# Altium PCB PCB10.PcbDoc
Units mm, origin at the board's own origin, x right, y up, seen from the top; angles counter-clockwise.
Board outline 101.6 x 53.34 mm, 4 copper layers (TOP, GND, SIG, BOTTOM), stack 1.586 mm thick; 82 components, 223 nets, 746 pads, 0 vias.
Unrouted connection lines stored in the file: 269.
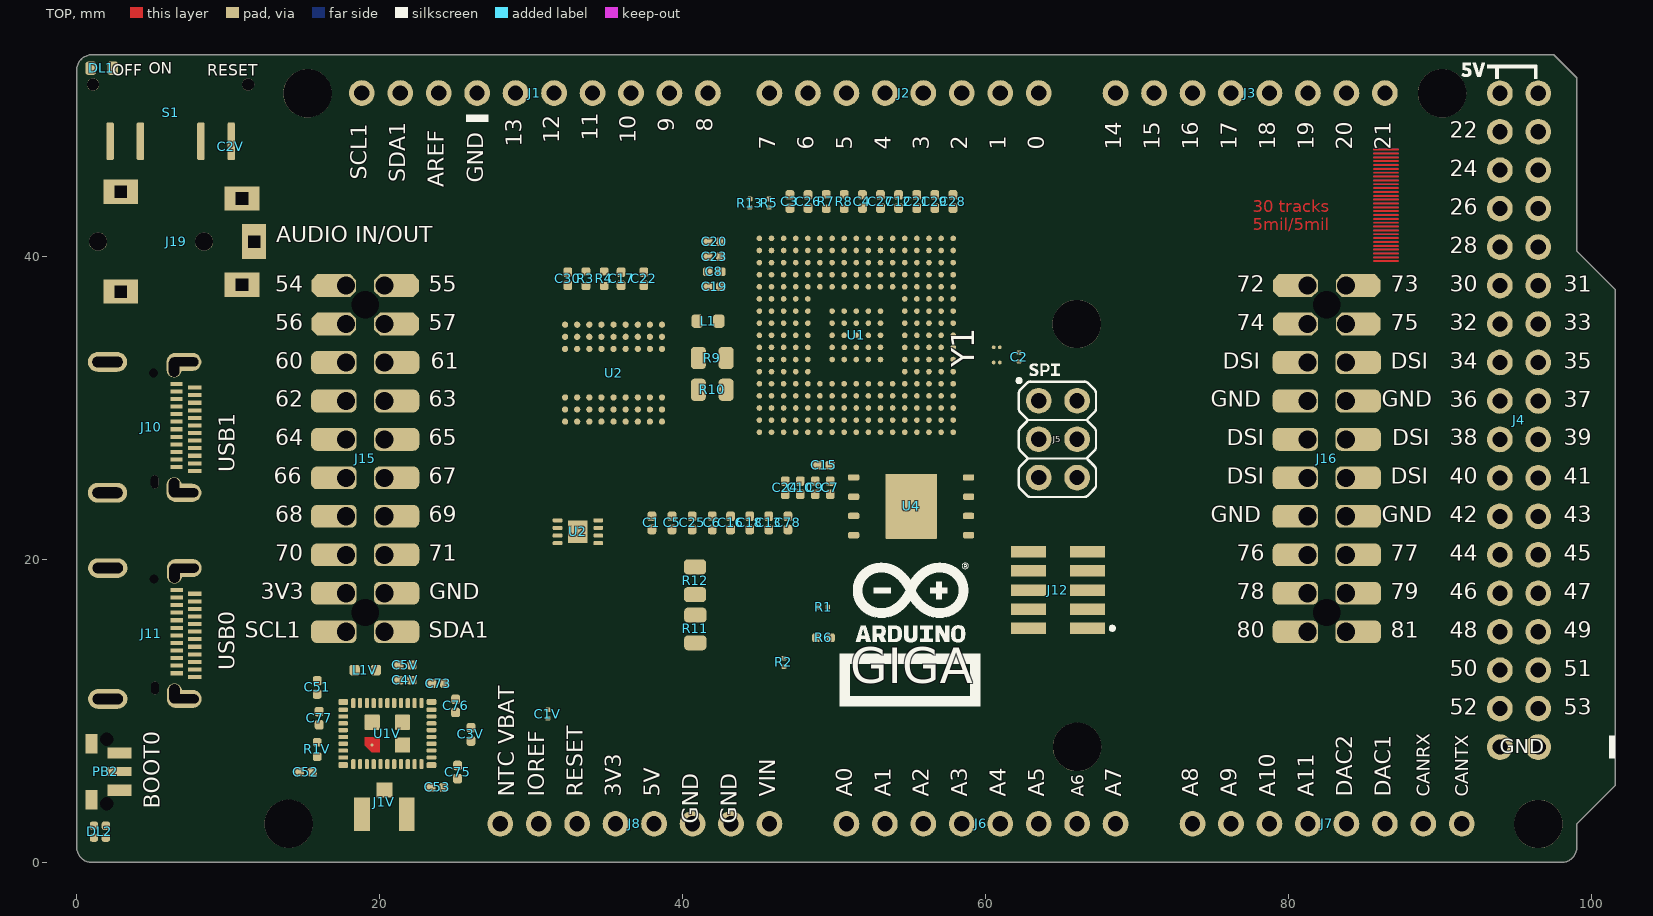
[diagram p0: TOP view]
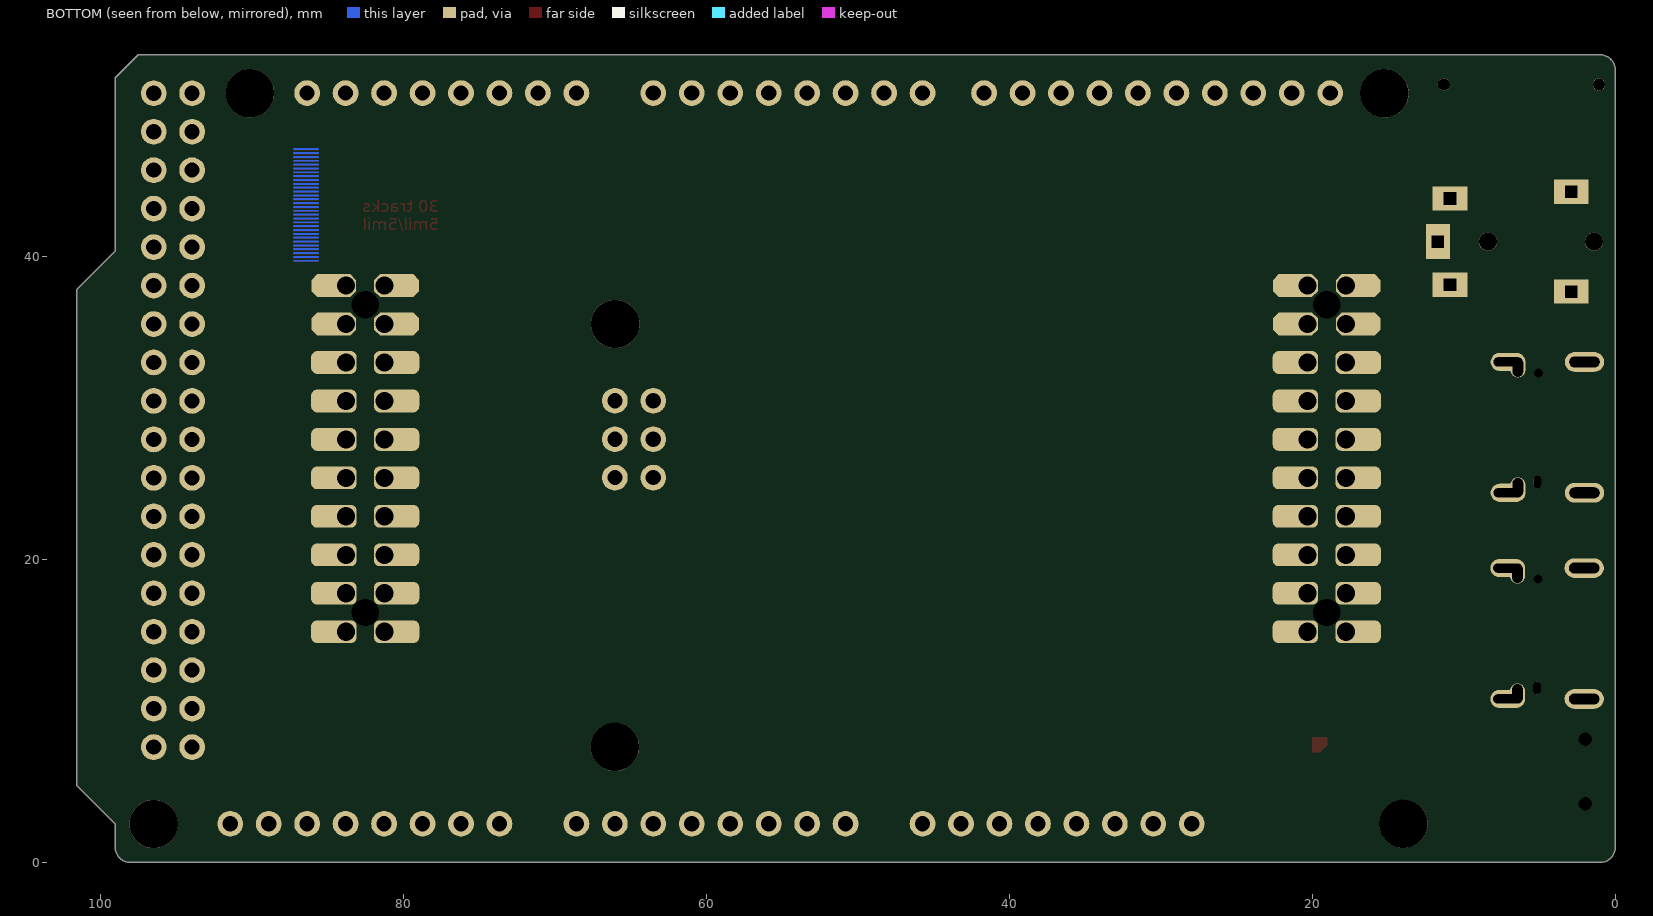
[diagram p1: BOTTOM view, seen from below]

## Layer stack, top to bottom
Top Solder: solder mask 0.0102, Solder Resist, Dk 3.5
TOP: signal copper 0.018
Dielectric 1: prepreg 0.14, PP-014, Dk 4.2
GND: signal copper 0.035
Dielectric2: core 1.2, FR-4, Dk 4.8
SIG: signal copper 0.035
Dielectric3: prepreg 0.14, PP-014, Dk 4.2
BOTTOM: signal copper 0.018
Bottom Solder: solder mask 0.0102, Solder Resist, Dk 3.5

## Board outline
0,1 0,52.34 cw(c1,52.34) 1,53.34 97.536,53.34 99.06,51.816 99.06,40.386 101.6,37.846 101.6,5.08 99.06,2.54 99.06,1 cw(c98.06,1) 98.06,0 1,0 cw(c1,1)

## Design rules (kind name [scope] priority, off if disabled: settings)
BoardOutlineClearance Silks [(OnLayer('Top Overlay') OR OnLayer('Bottom Overlay'))] p1: gap=0.1 ignorepadtopadclearanceinfootprint=FALSE
BoardOutlineClearance [All] p2: gap=0.3 ignorepadtopadclearanceinfootprint=FALSE
Clearance COPPER_0.3mm [All] p1: gap=0.127 ignorepadtopadclearanceinfootprint=FALSE except(0.3: Arc-Fill Arc-Poly Arc-Region Track-Fill Track-Poly Track-Region SMDPad-Fill SMDPad-Poly SMDPad-Region THPad-Fill THPad-Poly THPad-Region Via-Fill Via-Poly Via-Region Fill-Fill Fill-Poly Fill-Region Poly-Poly Poly-Region Region-Region)
Clearance "Generic clearance 0.127mm" [All] p2: gap=0.127 ignorepadtopadclearanceinfootprint=FALSE
ComponentClearance [All] p1: gap=0.2 collisioncheckmode=3 verticalgap=0 showdistances=TRUE
DiffPairsRouting USB [InDifferentialPairClass('USB')] p1: maxlimit=0.254 minlimit=0.15 mostfreqgap=0.254 toplayer_maxgap=0.15 toplayer_prefgap=0.15 toplayer_minwidth=0.15 toplayer_maxwidth=0.21 toplayer_prefwidth=0.2 midlayer2_mingap=0.24 midlayer2_maxgap=0.24 midlayer2_prefgap=0.24 midlayer2_minwidth=0.15 midlayer2_maxwidth=0.15 midlayer2_prefwidth=0.15 bottomlayer_maxgap=0.15 bottomlayer_prefgap=0.15 bottomlayer_minwidth=0.15 bottomlayer_maxwidth=0.21 bottomlayer_prefwidth=0.2 impedanceprofiledriven=TRUE impedanceprofileid={E6B00C31-4C8E-439C-824F-D2B2CDC26F9C} impedanceprofilevalue=90.000000 maxuncoupledlength=12.7
Height [All] p1: minheight=0 maxheight=30 prefheight=12.7
HoleSize [All] p1: absolutevalues=TRUE maxlimit=20 minlimit=0.3 maxpercent=80.000 minpercent=20.000
HoleToHoleClearance [All] p1: gap=0.25 allowstackedmicrovias=FALSE
MinimumAnnularRing [All] p1: minimumring=0.15
PlaneConnect [All] p1: pad.planeconnectstyle=Relief pad.reliefexpansion=0.508 pad.reliefentries=4 pad.reliefconductorwidth=0.254 pad.reliefairgap=0.254 via.planeconnectstyle=Direct via.reliefexpansion=0.508 via.reliefentries=4 via.reliefconductorwidth=0.254 via.reliefairgap=0.254
PolygonConnect [All] p1: thpad.connectstyle=Relief thpad.reliefconductorwidth=0.2 thpad.reliefentries=4 thpad.polygonreliefangle="90 Angle" thpad.airgapwidth=0.254 smdpad.connectstyle=Relief smdpad.reliefconductorwidth=0.2 smdpad.reliefentries=4 smdpad.polygonreliefangle="90 Angle" smdpad.airgapwidth=0.254 via.connectstyle=Direct via.reliefconductorwidth=0.254 via.reliefentries=4 via.polygonreliefangle="90 Angle" via.airgapwidth=0.254
RoomDefinition AUDIO [InComponentClass('AUDIO')] p1: confinementstyle=ConfineIn formatcopy=TRUE lockcomponents=FALSE outline 102.7,0.5 179.2,0.5 179.2,30 102.7,30
RoomDefinition Wifi [InComponentClass('Wifi')] p2: confinementstyle=ConfineIn formatcopy=TRUE lockcomponents=FALSE outline -40.4,-40.4 10.4,-40.4 10.4,-15 -40.4,-15
RoomDefinition TOP [InComponentClass('TOP')] p3: confinementstyle=ConfineIn formatcopy=TRUE lockcomponents=FALSE outline 102.7,1.5 112.4,1.5 112.4,12.5 102.7,12.5
RoomDefinition HEADERS [InComponentClass('HEADERS')] p4: confinementstyle=ConfineIn formatcopy=TRUE lockcomponents=FALSE outline 103.6,3.6 145.6,3.6 145.6,51.6 103.6,51.6
RoomDefinition STM32H747 [InComponentClass('STM32H747')] p5: confinementstyle=ConfineIn formatcopy=TRUE lockcomponents=FALSE outline 57.6,-10.4 61.6,-10.4 61.6,-6.4 57.6,-6.4
RoutingVias StandardVias [All] p1: holewidth=0.2 width=0.4 viastyle="Through Hole" minholewidth=0.2 minwidth=0.4 maxholewidth=0.2 maxwidth=0.4
SMDToCorner [All] p1: distance=39370
SilkToSilkClearance [All] p1: silktosilkclearance=0.2
SilkToSolderMaskClearance [IsPad] p1: minsilkscreentomaskgap=0.15 clearancetoexposedcopper=TRUE
SolderMaskExpansion VIAtented [IsVia] p1: expansion=0.102 istentingtop=TRUE
SolderMaskExpansion [All] p2: expansion=0.05 istentingtop=FALSE
UnRoutedNet [All] p1: checkbadconnections=TRUE
ViasUnderSMD [All] p1: allowed=FALSE
Width StandardTraces [All] p1: maxlimit=5 minlimit=0.127 preferedwidth=0.15
21 further rules are at their usual default settings.

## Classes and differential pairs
component class AUDIO: J19
net class "50 ohm": NetC1V_1 NetC2V_1
component class Wifi: C1V C2V C3V C4V C5V J1V L1V R1V R18 U1V
component class TOP: J10 J11 PB2 S1
component class HEADERS: J1 J2 J3 J4 J5 J6 J7 J8 J12 J15 J16
component class STM32H747: C1 C2 C3 C4 C5 C6 C7 C8 C9 C10 C12 C13 C15 C16 C17 C18 C19 C20 C21 C22 C23 C24 C25 C26 C27 C28 C29 C30 C51 C52 C53 C73 C75 C76 C77 C78 DL1 DL2 L1 R1 R2 R3 R4 R5 R6 R7 R8 R9 R10 R11 R12 R13 U1 U2 U4 Y1

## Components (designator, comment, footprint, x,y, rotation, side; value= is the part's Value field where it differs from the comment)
C1 "CBR04C220F5GAC" CAP-0402 37.98,22.424 r90 top value=22pF
C1V "DNP" CAP-0201 31.115,9.8 r270 top
C2 "C0201C104K9PACTU" CAP-0201 62.23,33.38 r270 top value=100nF
C2V "DNP" CAP-0201 10.16,47.265 r270 top
C3 "GRM155R60J106ME05D" CAP-0402 47.099,43.648 r270 top value=10µF
C3V "GRM155R60J225KE95D" CAP-0402 26.035,8.455 r270 top value=2.2µF
C4 "GRM155R60J225KE95D" CAP-0402 51.883,43.648 r270 top value=2.2µF
C4V "GRM155R60J475ME47D" CAP-0402 21.702,12.036 r0 top value=4.7µF
C5 "GRM155R60J225KE95D" CAP-0402 39.31,22.424 r90 top value=2.2µF
C5V "GRM155R60J475ME47D" CAP-0402 21.702,13.036 r0 top value=4.7µF
C6 "GRM155R60J225KE95D" CAP-0402 41.97,22.424 r90 top value=2.2µF
C7 "GRM155R61H104KE19D" CAP-0402 49.762,24.748 r90 top value=100nF
C8 "GRM155R61H104KE19D" CAP-0402 42.105,39.013 r0 top value=100nF
C9 "GRM155R61H104KE19D" CAP-0402 48.772,24.748 r90 top value=100nF
C10 "GRM155R61H104KE19D" CAP-0402 47.782,24.748 r90 top value=100nF
C12 "CBR04C220F5GAC" CAP-0402 54.276,43.648 r270 top value=22pF
C13 "GRM155R61H104KE19D" CAP-0402 45.701,22.424 r270 top value=100nF
C15 "GRM155R61H104KE19D" CAP-0402 49.315,26.23 r180 top value=100nF
C16 "GRM155R61H104KE19D" CAP-0402 43.18,22.424 r270 top value=100nF
C17 "GRM155R61H104KE19D" CAP-0402 35.948,38.548 r90 top value=100nF
C18 "GRM155R61H104KE19D" CAP-0402 44.441,22.424 r270 top value=100nF
C19 "GRM155R61H104KE19D" CAP-0402 42.104,38.023 r0 top value=100nF
C20 "GRM155R61H104KE19D" CAP-0402 42.105,40.993 r0 top value=100nF
C21 "GRM155R61H104KE19D" CAP-0402 55.472,43.648 r270 top value=100nF
C22 "GRM155R61H104KE19D" CAP-0402 37.448,38.548 r90 top value=100nF
C23 "GRM155R61H104KE19D" CAP-0402 42.105,40.003 r0 top value=100nF
C24 "GRM155R61H104KE19D" CAP-0402 46.792,24.748 r90 top value=100nF
C25 "GRM155R60J225KE95D" CAP-0402 40.64,22.424 r90 top value=2.2µF
C26 "GRM155R60J225KE95D" CAP-0402 48.295,43.648 r270 top value=2.2µF
C27 "GRM155R60J225KE95D" CAP-0402 53.08,43.648 r270 top value=2.2µF
C28 "GRM155R61H104KE19D" CAP-0402 57.864,43.648 r270 top value=100nF
C29 "GRM155R61H104KE19D" CAP-0402 56.668,43.648 r270 top value=100nF
C30 "GRM155R60J106ME05D" CAP-0402 32.428,38.548 r270 top value=10µF
C51 "GRM155R61H104KE19D" CAP-0402 15.875,11.557 r90 top value=100nF
C52 "GRM155R61H104KE19D" CAP-0402 15.113,5.969 r180 top value=100nF
C53 "GRM155R61H104KE19D" CAP-0402 23.803,4.953 r180 top value=100nF
C73 "GRM155R61H104KE19D" CAP-0402 23.876,11.811 r180 top value=100nF
C75 "GRM155R61H104KE19D" CAP-0402 25.146,5.969 r90 top value=100nF
C76 "GRM155R61H104KE19D" CAP-0402 25.019,10.341 r270 top value=100nF
C77 "GRM155R61H104KE19D" CAP-0402 16.002,9.525 r270 top value=100nF
C78 "GRM155R61H104KE19D" CAP-0402 46.962,22.424 r270 top value=100nF
DL1 "HSMD-C190" LEDC1608X80N-AK 1.651,52.451 r180 top
DL2 "SMLP34RGB2W3" SMLP34RGB2W 1.524,2.032 r270 top
J1 "HEADER TH 2.54mm VERT. 1x010POS" "PIN HEADER 2.54mm VERT. 1x10POS" 30.252,50.813 r0 top
J1V "U.FL-R-SMT-1(60)" U.FL-R-SMT-1(60)-1 20.32,3.175 r180 top
J2 "HEADER TH 2.54mm VERT. 1x008POS" "PIN HEADER 2.54mm VERT. 1x8POS" 54.636,50.813 r0 top
J3 "HEADER TH 2.54mm VERT. 1x008POS" "PIN HEADER 2.54mm VERT. 1x8POS" 77.496,50.813 r0 top
J4 "HEADER TH 2.54mm VERT. 2x018POS" "PIN HEADER 2.54mm VERT. 2x6POS" 95.25,29.209 r270 top
J5 "HEADER TH 2.54mm VERT. 2x003POS" "HEADER TH 2.54mm VERT. 2x003POS-Footprint-1" 64.796,27.953 r270 top
J6 "HEADER TH 2.54mm VERT. 1x008POS" "PIN HEADER 2.54mm VERT. 1x8POS" 59.716,2.553 r0 top
J7 "HEADER TH 2.54mm VERT. 1x008POS" "PIN HEADER 2.54mm VERT. 1x8POS" 82.576,2.553 r0 top
J8 "HEADER TH 2.54mm VERT. 1x008POS" "PIN HEADER 2.54mm VERT. 1x8POS" 36.856,2.553 r0 top
J10 "CX90B1-24P" CX90B1-24P 5.08,28.735 r270 top
J11 "CX90B1-24P" CX90B1-24P 5.1,15.12 r270 top
J12 "FTSH-105-01-F-DV" FTSH-105-01-F-DV-Footprint-1 64.796,17.993 r90 top
J15 "HLE-110-02-F-DV" HLE-110-02-F-DV 19.05,26.669 r270 top
J16 "HLE-110-02-F-DV" HLE-110-02-F-DV 82.55,26.669 r270 top
J19 "54-00174" 54-00174-Footprint-1 11.71,41 r0 top
L1 "FBMJ1608HM180NTR" L-0603 41.69,35.743 r0 top
L1V "LQM18PN2R2MGHD" FP-LQM18PN_GH-IPC_C 19.05,12.7 r180 top value=2.2uH
PB2 "TL3340AF160QG" TL3340AF160QG-Footprint-1 1.905,6 r270 top
R1 "AC0201FR-07330RL" RES-0201 49.315,16.87 r0 top value=330
R1V "CRCW04020000Z0EDC" RES-0402 15.875,7.46 r270 top value=0
R2 "AC0201FR-07330RL" RES-0201 46.695,13.215 r270 top value=330
R3 "CRCW04020000Z0EDC" RES-0402 33.628,38.548 r90 top value=0
R4 "CRCW0402100KFKEDC" RES-0402 34.828,38.548 r90 top value=100k
R5 "AC0201FR-07330RL" RES-0201 45.72,43.54 r90 top value=330
R6 "CRCW0402100KFKEDC" RES-0402 49.315,14.843 r180 top value=100k
R7 "CRCW04020000Z0EDC" RES-0402 49.491,43.648 r270 top value=0
R8 "CRCW04020000Z0EDC" RES-0402 50.687,43.648 r270 top value=0
R9 "CRCW08050000Z0EB" RES-0805 41.965,33.313 r180 top value=0
R10 "CRCW08050000Z0EB" RES-0805 41.965,31.213 r180 top value=0
R11 "CRCW08050000Z0EB" RES-0805 40.849,15.42 r90 top value=0
R12 "CRCW08050000Z0EB" RES-0805 40.831,18.601 r270 top value=0
R13 "AC0201FR-07330RL" RES-0201 44.45,43.54 r270 top value=330
S1 "JSM07011SAQNR" JSM07011SAQNR-Footprint-1 6.2,47.625 r180 top
U1 "STM32H747XIH6" STM32H747XIH6-Footprint-1 51.48,34.813 r270 top
U1V "LBEE5KL1DX-883" LBEE5KL1DX-883 20.51,8.513 r0 top
U2 "AS4C4M16SA-6BIN" AS4C4M16SA-7BCN-Footprint-1 35.448,32.313 r0 top
U2 "ATECC608A-MAHDA-T" UDFN8 33.095,21.84 r90 top
U4 "MX25L12833FZ2I-10G" WSON8-1 55.103,23.52 r270 top
Y1 "SIT1532AI-J4-DCC-32.768E" SiT1532AI-J4-DCC-32.768E-Footprint-1 60.755,33.52 r270 top

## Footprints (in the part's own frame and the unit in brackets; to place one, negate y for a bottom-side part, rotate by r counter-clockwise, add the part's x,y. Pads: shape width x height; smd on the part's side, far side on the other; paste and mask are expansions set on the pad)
54-00174-Footprint-1 [mm]
  rect 1.6x2.3 hole 0.8 square unplated: 1(0,0)
  rect 2.3x1.6 hole 0.8 square unplated: 2(-0.8,2.85) 3(-0.8,-2.85) 4(-8.8,-3.3) 4(-8.8,3.3)
  round 1.2 hole 1.2 unplated mask+0.2: NC1(-3.3,0) NC2(-10.3,0)
  body extent -14.74,-3.5 0.26,3.6, height 6.13
AS4C4M16SA-7BCN-Footprint-1 [mm]
  round 0.41 smd: A1(-3.2,-3.2) A2(-3.2,-2.4) A3(-3.2,-1.6) A7(-3.2,1.6) A8(-3.2,2.4) A9(-3.2,3.2) B1(-2.4,-3.2) B2(-2.4,-2.4) B3(-2.4,-1.6) B7(-2.4,1.6) B8(-2.4,2.4) B9(-2.4,3.2) C1(-1.6,-3.2) C2(-1.6,-2.4) C3(-1.6,-1.6) C7(-1.6,1.6) C8(-1.6,2.4) C9(-1.6,3.2) D1(-0.8,-3.2) D2(-0.8,-2.4) D3(-0.8,-1.6) D7(-0.8,1.6) D8(-0.8,2.4) D9(-0.8,3.2) E1(0,-3.2) E2(0,-2.4) E3(0,-1.6) E7(0,1.6) E8(0,2.4) E9(0,3.2) F1(0.8,-3.2) F2(0.8,-2.4) F3(0.8,-1.6) F7(0.8,1.6) F8(0.8,2.4) F9(0.8,3.2) G1(1.6,-3.2) G2(1.6,-2.4) G3(1.6,-1.6) G7(1.6,1.6) G8(1.6,2.4) G9(1.6,3.2) H1(2.4,-3.2) H2(2.4,-2.4) H3(2.4,-1.6) H7(2.4,1.6) H8(2.4,2.4) H9(2.4,3.2) J1(3.2,-3.2) J2(3.2,-2.4) J3(3.2,-1.6) J7(3.2,1.6) J8(3.2,2.4) J9(3.2,3.2)
  body extent -4,-4 4,4, height 1.15
CAP-0201 [mm] "Chip Capacitor, 2-Leads, Body 0201 (in) 0603 (mm) IPC Medium Density"
  rrect52% 0.31x0.34 smd mask+0: 1(-0.275,0) 2(0.275,0)
  body extent -0.3,-0.15 0.3,0.15, height 0.3
CAP-0402 [mm] "Chip Capacitor, 2-Leads, Body  0402 (in) 1005 (mm), IPC Medium Density"
  rrect52% 0.63x0.58 smd mask+0: 1(-0.435,0) 2(0.435,0)
  body extent -0.5,-0.25 0.5,0.25, height 0.5
CX90B1-24P [mm] "CONN USB TYPEC"
  rect 0.27x0.9 smd mask+0.04: A1(-2.625,2.7) A2(-2.125,2.7) A3(-1.625,2.7) A4(-1.125,2.7) A5(-0.625,2.7) A6(-0.125,2.7) A7(0.375,2.7) A8(0.875,2.7) A9(1.375,2.7) A10(1.875,2.7) A11(2.375,2.7) A12(2.875,2.7)
  rect 0.27x0.8 smd mask+0.04: B1(2.625,1.5) B2(2.125,1.5) B3(1.625,1.5) B4(1.125,1.5) B5(0.625,1.5) B6(0.125,1.499) B7(-0.375,1.5) B8(-0.875,1.5) B9(-1.375,1.5) B10(-1.875,1.5) B11(-2.375,1.5) B12(-2.875,1.5)
  round 0 hole 0.6 unplated: FIXING(-3.6,0)
  oval 0.85x0.5 hole 0.5 slot 0.85 at 0 deg unplated mask+0: FIXING(3.6,0.065)
  oval 1.2x2.3 hole 0.6 slot 1.9 at 90 deg: SHIELD1(-4.32,2) SHIELD2(4.32,2)
  oval 1.35x1 hole 0.7 slot 1.25 at 0 deg: SHIELD1(-3.97,1.35) SHIELD2(3.97,1.35)
  oval 1.3x2.6 hole 0.7 slot 2 at 90 deg: SHIELD3(-4.32,-3.05) SHIELD4(4.32,-3.05)
  body extent -4.46,-5.4 4.48,2.75, height 3.19
FP-LQM18PN_GH-IPC_C [mm]
  rrect50% 0.7x0.7 smd: 1(-0.7,0) 2(0.7,0)
  body extent -0.8,-0.4 0.8,0.4, height 1
FTSH-105-01-F-DV-Footprint-1 [mm]
  rect 0.76x2.3 smd: 1(-2.54,-1.95) 2(-2.54,1.95) 3(-1.27,-1.95) 4(-1.27,1.95) 5(0,-1.95) 6(0,1.95) 7(1.27,-1.95) 8(1.27,1.95) 9(2.54,-1.95) 10(2.54,1.95)
  body extent -3.17,-2.92 3.17,2.92, height 5.98
"HEADER TH 2.54mm VERT. 2x003POS-Footprint-1" [mm]
  round 1.7 hole 1 mask+0.2: 1(-2.54,-1.27) 2(-2.54,1.27) 3(0,-1.27) 4(0,1.27) 5(2.54,-1.27) 6(2.54,1.27)
HLE-110-02-F-DV [mm]
  round 0 hole 1.8 unplated paste-5: 0(-10.16,0) 0(10.16,0)
  oct 1.5x2.95 hole 1.2 copper offset 0,-0.8 mask+0.02: 1(-11.43,-1.27) 3(-8.89,-1.27)
  oct 1.5x2.95 hole 1.2 copper offset 0,0.8 mask+0.02: 2(-11.43,1.27) 4(-8.89,1.27)
  rrect50% 1.5x3 hole 1.2 copper offset 0,-0.8 mask+0.02: 5(-6.35,-1.27) 7(-3.81,-1.27) 9(-1.27,-1.27) 11(1.27,-1.27) 13(3.81,-1.27) 15(6.356,-1.27) 17(8.89,-1.27) 19(11.43,-1.27)
  rrect50% 1.5x3 hole 1.2 copper offset 0,0.8 mask+0.02: 6(-6.35,1.27) 8(-3.81,1.27) 10(-1.27,1.27) 12(1.27,1.27) 14(3.81,1.27) 16(6.356,1.27) 18(8.89,1.27) 20(11.43,1.27)
  body extent -12.7,-3.29 12.7,3.29, height 3.71
JSM07011SAQNR-Footprint-1 [mm] "Default PCB Component"
  rrect50% 0.5x2.5 smd mask+0.05: 1(-4,0) 2(-2,0) 3(2,0) 4(4,0)
  round 0.8 hole 0.8 unplated mask+0: ""(-5.125,-3.75) ""(5.125,-3.75)
  body extent -6.28,-5.66 6.22,0.84, height 2.1
L-0603 [mm] "Chip Inductor - Body 0603 imperial,1.6x0.8mm, IPC High Density"
  rrect51% 0.75x0.87 smd mask+0: 1(-0.71,0) 2(0.71,0)
  body extent -0.8,-0.4 0.8,0.4, height 0.8
LBEE5KL1DX-883 [mm]
  rrect50% 0.28x0.64 smd mask+0.05: 1(-2.25,-2.015) 2(-1.8,-2.015) 3(-1.35,-2.015) 4(-0.9,-2.015) 5(-0.45,-2.015) 6(0,-2.015) 7(0.45,-2.015) 8(0.9,-2.015) 9(1.35,-2.015) 10(1.8,-2.015) 11(2.25,-2.015) 22(2.25,2.015) 23(1.8,2.015) 24(1.35,2.015) 25(0.9,2.015) 26(0.45,2.015) 27(0,2.015) 28(-0.45,2.015) 29(-0.9,2.015) 30(-1.35,2.015) 31(-1.8,2.015) 32(-2.25,2.015)
  rrect50% 0.64x0.4 smd mask+0.05: 12(2.915,-2.087) 21(2.915,2.087) 33(-2.915,2.087) 42(-2.915,-2.087)
  rrect50% 0.64x0.28 smd mask+0.05: 13(2.915,-1.575) 14(2.915,-1.125) 15(2.915,-0.675) 16(2.915,-0.225) 17(2.915,0.225) 18(2.915,0.675) 19(2.915,1.125) 20(2.915,1.575) 34(-2.915,1.575) 35(-2.915,1.125) 36(-2.915,0.675) 37(-2.915,0.225) 38(-2.915,-0.225) 39(-2.915,-0.675) 40(-2.915,-1.125) 41(-2.915,-1.575)
  round 0.2 smd paste+0 mask+0.05: 43(-1,-0.75)
  rrect10% 1x1 smd mask+0.05: 44(1,-0.75) 45(-1,0.75) 46(1,0.75)
  TOP region: -1.485,-0.765 -1.496,-0.748 -1.5,-0.729 -1.5,-0.729 -1.5,-0.3 -1.496,-0.281 -1.485,-0.265 -1.469,-0.254 -1.45,-0.25 -1.45,-0.25 -0.55,-0.25 -0.531,-0.254 -0.515,-0.265 -0.504,-0.281 -0.5,-0.3 -0.5,-0.3 -0.5,-1.2 -0.504,-1.219 -0.515,-1.235 -0.531,-1.246 -0.55,-1.25 -0.55,-1.25 -0.979,-1.25 -0.998,-1.246 -1.015,-1.235 -1.015,-1.235
  body extent -3.47,-2.57 3.48,2.58, height 1.1
LEDC1608X80N-AK [mm]
  rrect50% 0.72x0.87 smd: A(0.725,0) C(-0.725,0)
  body extent -0.8,-0.4 0.8,0.4, height 0.79
"PIN HEADER 2.54mm VERT. 1x8POS" [mm]
  round 1.7 hole 1 mask+0.2: 1(-8.89,0) 2(-6.35,0) 3(-3.81,0) 4(-1.27,0) 5(1.27,0) 6(3.81,0) 7(6.35,0) 8(8.89,0)
"PIN HEADER 2.54mm VERT. 1x10POS" [mm]
  round 1.7 hole 1 mask+0.2: 1(-11.43,0) 2(-8.89,0) 3(-6.35,0) 4(-3.81,0) 5(-1.27,0) 6(1.27,0) 7(3.81,0) 8(6.35,0) 9(8.89,0) 10(11.43,0)
"PIN HEADER 2.54mm VERT. 2x6POS" [mm]
  round 1.7 hole 1 mask+0.2: 1(-21.59,-1.27) 2(-21.59,1.27) 3(-19.05,-1.27) 4(-19.05,1.27) 5(-16.51,-1.27) 6(-16.51,1.27) 7(-13.97,-1.27) 8(-13.97,1.27) 9(-11.43,-1.27) 10(-11.43,1.27) 11(-8.89,-1.27) 12(-8.89,1.27) 13(-6.35,-1.27) 14(-6.35,1.27) 15(-3.81,-1.27) 16(-3.81,1.27) 17(-1.27,-1.27) 18(-1.27,1.27) 19(1.27,-1.27) 20(1.27,1.27) 21(3.81,-1.27) 22(3.81,1.27) 23(6.35,-1.27) 24(6.35,1.27) 25(8.89,-1.27) 26(8.89,1.27) 27(11.43,-1.27) 28(11.43,1.27) 29(13.97,-1.27) 30(13.97,1.27) 31(16.51,-1.27) 32(16.51,1.27) 33(19.05,-1.27) 34(19.05,1.27) 35(21.59,-1.27) 36(21.59,1.27)
RES-0201 [mm] "Chip Resistor, 2-Leads, Body 0201 (in) 0603 (mm) IPC Medium Density"
  rrect52% 0.31x0.34 smd mask+0: 1(-0.275,0) 2(0.275,0)
  body extent -0.3,-0.15 0.3,0.15, height 0.24
RES-0402 [mm] "Chip Resistor, 2-Leads, Body  0402 (in) 1005 (mm), IPC Medium Density"
  rrect51% 0.55x0.58 smd mask+0: 1(-0.475,0) 2(0.475,0)
  body extent -0.5,-0.25 0.5,0.25, height 0.34
RES-0805 [mm] "Chip Resistor - Body 0805 imperial, 2.0x1.2mm, IPC Medium Density"
  rrect51% 0.99x1.47 smd paste-1.47 mask+0: 1(-0.915,0) 2(0.915,0)
  body extent -1,-0.62 1,0.63, height 0.58
SiT1532AI-J4-DCC-32.768E-Footprint-1 [mm]
  round 0.25 smd: 1(-0.5,-0.205) 2(0.5,-0.205) 3(0.5,0.205) 4(-0.5,0.205)
  body extent -0.77,-0.42 0.77,0.42, height 0.55
SMLP34RGB2W [mm]
  rrect52% 0.54x0.54 smd: 1(-0.395,-0.395) 2(-0.395,0.395) 3(0.395,0.395) 4(0.395,-0.395)
  body extent -0.5,-0.5 0.5,0.5, height 0.2
STM32H747XIH6-Footprint-1 [mm]
  round 0.37 smd: A1(-6.4,-6.4) A2(-6.4,-5.6) A3(-6.4,-4.8) A4(-6.4,-4) A5(-6.4,-3.2) A6(-6.4,-2.4) A7(-6.4,-1.6) A8(-6.4,-0.8) A9(-6.4,0) A10(-6.4,0.8) A11(-6.4,1.6) A12(-6.4,2.4) A13(-6.4,3.2) A14(-6.4,4) A15(-6.4,4.8) A16(-6.4,5.6) A17(-6.4,6.4) B1(-5.6,-6.4) B2(-5.6,-5.6) B3(-5.6,-4.8) B4(-5.6,-4) B5(-5.6,-3.2) B6(-5.6,-2.4) B7(-5.6,-1.6) B8(-5.6,-0.8) B9(-5.6,0) B10(-5.6,0.8) B11(-5.6,1.6) B12(-5.6,2.4) B13(-5.6,3.2) B14(-5.6,4) B15(-5.6,4.8) B16(-5.6,5.6) B17(-5.6,6.4) C1(-4.8,-6.4) C2(-4.8,-5.6) C3(-4.8,-4.8) C4(-4.8,-4) C5(-4.8,-3.2) C6(-4.8,-2.4) C7(-4.8,-1.6) C8(-4.8,-0.8) C9(-4.8,0) C10(-4.8,0.8) C11(-4.8,1.6) C12(-4.8,2.4) C13(-4.8,3.2) C14(-4.8,4) C15(-4.8,4.8) C16(-4.8,5.6) C17(-4.8,6.4) D1(-4,-6.4) D2(-4,-5.6) D3(-4,-4.8) D4(-4,-4) D5(-4,-3.2) D6(-4,-2.4) D7(-4,-1.6) D8(-4,-0.8) D9(-4,0) D10(-4,0.8) D11(-4,1.6) D12(-4,2.4) D13(-4,3.2) D14(-4,4) D15(-4,4.8) D16(-4,5.6) D17(-4,6.4) E1(-3.2,-6.4) E2(-3.2,-5.6) E3(-3.2,-4.8) E4(-3.2,-4) E5(-3.2,-3.2) E6(-3.2,-2.4) E7(-3.2,-1.6) E8(-3.2,-0.8) E9(-3.2,0) E10(-3.2,0.8) E11(-3.2,1.6) E12(-3.2,2.4) E13(-3.2,3.2) E14(-3.2,4) E15(-3.2,4.8) E16(-3.2,5.6) E17(-3.2,6.4) F1(-2.4,-6.4) F2(-2.4,-5.6) F3(-2.4,-4.8) F4(-2.4,-4) F5(-2.4,-3.2) F13(-2.4,3.2) F14(-2.4,4) F15(-2.4,4.8) F16(-2.4,5.6) F17(-2.4,6.4) G1(-1.6,-6.4) G2(-1.6,-5.6) G3(-1.6,-4.8) G4(-1.6,-4) G5(-1.6,-3.2) G7(-1.6,-1.6) G8(-1.6,-0.8) G9(-1.6,0) G10(-1.6,0.8) G11(-1.6,1.6) G13(-1.6,3.2) G14(-1.6,4) G15(-1.6,4.8) G16(-1.6,5.6) G17(-1.6,6.4) H1(-0.8,-6.4) H2(-0.8,-5.6) H3(-0.8,-4.8) H4(-0.8,-4) H5(-0.8,-3.2) H7(-0.8,-1.6) H8(-0.8,-0.8) H9(-0.8,0) H10(-0.8,0.8) H11(-0.8,1.6) H13(-0.8,3.2) H14(-0.8,4) H15(-0.8,4.8) H16(-0.8,5.6) H17(-0.8,6.4) J1(0,-6.4) J2(0,-5.6) J3(0,-4.8) J4(0,-4) J5(0,-3.2) J7(0,-1.6) J8(0,-0.8) J9(0,0) J10(0,0.8) J11(0,1.6) J13(0,3.2) J14(0,4) J15(0,4.8) J16(0,5.6) J17(0,6.4) K1(0.8,-6.4) K2(0.8,-5.6) K3(0.8,-4.8) K4(0.8,-4) K5(0.8,-3.2) K7(0.8,-1.6) K8(0.8,-0.8) K9(0.8,0) K10(0.8,0.8) K11(0.8,1.6) K13(0.8,3.2) K14(0.8,4) K15(0.8,4.8) K16(0.8,5.6) K17(0.8,6.4) L1(1.6,-6.4) L2(1.6,-5.6) L3(1.6,-4.8) L4(1.6,-4) L5(1.6,-3.2) L7(1.6,-1.6) L8(1.6,-0.8) L9(1.6,0) L10(1.6,0.8) L11(1.6,1.6) L13(1.6,3.2) L14(1.6,4) L15(1.6,4.8) L16(1.6,5.6) L17(1.6,6.4) M1(2.4,-6.4) M2(2.4,-5.6) M3(2.4,-4.8) M4(2.4,-4) M5(2.4,-3.2) M13(2.4,3.2) M14(2.4,4) M15(2.4,4.8) M16(2.4,5.6) M17(2.4,6.4) N1(3.2,-6.4) N2(3.2,-5.6) N3(3.2,-4.8) N4(3.2,-4) N5(3.2,-3.2) N6(3.2,-2.4) N7(3.2,-1.6) N8(3.2,-0.8) N9(3.2,0) N10(3.2,0.8) N11(3.2,1.6) N12(3.2,2.4) N13(3.2,3.2) N14(3.2,4) N15(3.2,4.8) N16(3.2,5.6) N17(3.2,6.4) P1(4,-6.4) P2(4,-5.6) P3(4,-4.8) P4(4,-4) P5(4,-3.2) P6(4,-2.4) P7(4,-1.6) P8(4,-0.8) P9(4,0) P10(4,0.8) P11(4,1.6) P12(4,2.4) P13(4,3.2) P14(4,4) P15(4,4.8) P16(4,5.6) P17(4,6.4) R1(4.8,-6.4) R2(4.8,-5.6) R3(4.8,-4.8) R4(4.8,-4) R5(4.8,-3.2) R6(4.8,-2.4) R7(4.8,-1.6) R8(4.8,-0.8) R9(4.8,0) R10(4.8,0.8) R11(4.8,1.6) R12(4.8,2.4) R13(4.8,3.2) R14(4.8,4) R15(4.8,4.8) R16(4.8,5.6) R17(4.8,6.4) T1(5.6,-6.4) T2(5.6,-5.6) T3(5.6,-4.8) T4(5.6,-4) T5(5.6,-3.2) T6(5.6,-2.4) T7(5.6,-1.6) T8(5.6,-0.8) T9(5.6,0) T10(5.6,0.8) T11(5.6,1.6) T12(5.6,2.4) T13(5.6,3.2) T14(5.6,4) T15(5.6,4.8) T16(5.6,5.6) T17(5.6,6.4) U1(6.4,-6.4) U2(6.4,-5.6) U3(6.4,-4.8) U4(6.4,-4) U5(6.4,-3.2) U6(6.4,-2.4) U7(6.4,-1.6) U8(6.4,-0.8) U9(6.4,0) U10(6.4,0.8) U11(6.4,1.6) U12(6.4,2.4) U13(6.4,3.2) U14(6.4,4) U15(6.4,4.8) U16(6.4,5.6) U17(6.4,6.4)
  body extent -7,-7 7,7, height 1.06
TL3340AF160QG-Footprint-1 [mm]
  rect 0.75x1.6 smd mask+0.05: 1(-1.225,0.925) 3(1.225,0.925)
  rect 0.6x1.6 smd mask+0.05: 2(0,0.925)
  rect 1.3x0.8 smd mask+0.05: MNT(-1.85,-0.925) MNT(1.85,-0.925)
  round 0.5 hole 0.9 unplated: NC1(-2.125,0.075) NC2(2.125,0.075)
  body extent -2.25,-1.98 2.25,1.69, height 3.3
U.FL-R-SMT-1(60)-1 [mm]
  rect 1.05x2.2 smd paste-3: GND(-1.475,0) GND(1.475,0)
  rect 1.05x1 smd paste-3: SIG(0,-1.6)
  body extent -1.5,-1.55 1.5,1.55, height 1.25
UDFN8 [mm] "QFN, 8-Leads, Body 3.00x2.00mm, Pitch 0.50mm, Thermal Pad 1.30x1.50mm, IPC Medium Density"
  rrect54% 0.26x0.64 smd paste+0 mask+0: 1(-0.75,-1.345) 2(-0.25,-1.345) 3(0.25,-1.345) 4(0.75,-1.345) 5(0.75,1.345) 6(0.25,1.345) 7(-0.25,1.345) 8(-0.75,1.345)
  rrect8% 1.5x1.3 smd paste-1.5 mask+0: 9(0,0)
  body extent -1,-1.5 1,1.5, height 0.55
WSON8-1 [mm]
  rrect52% 0.42x0.74 smd paste+0 mask+0: 1(-1.905,-3.795) 2(-0.635,-3.795) 3(0.635,-3.795) 4(1.905,-3.795) 5(1.905,3.795) 6(0.635,3.795) 7(-0.635,3.795) 8(-1.905,3.795)
  rrect3% 4.3x3.4 smd paste-4.3 mask+0: 9(0,0)
  body extent -3,-4 3,4, height 0.75

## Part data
C1 C12: library part C0028-A.9, "CAP CHIP 0402 22pF 50V C0G 1%", Case Code (Imperial)=0402, Case Code (Metric)=1005, Dielectric=C0G, Manufacturer=KEMET, Manufacturer 2=AVX, Manufacturer Part Number 2=04025U220FAT2A, Tolerance=1%, Voltage=50V
C1V C2V: library part UT0015-A.3, "DNP CAP CHIP 0201"
C2: library part C0001-A.3, "CAP CHIP 0201 100nF 6.3V X5R 10%", Case Code (Imperial)=0201, Case Code (Metric)=0603, Dielectric=X5R, Manufacturer=KEMET, Manufacturer 2=AVX, Manufacturer Part Number 2=02016D104KAT2A, Tolerance=10%, Voltage=6.3V
C3 C30: library part C0091-A.8, "CAP CHIP 0402 10UF X5R 6.3V 20%", Case Code (Imperial)=0402, Case Code (Metric)=1005, Dielectric=X5R, Manufacturer=Murata, Tolerance=20%, Voltage=6.3V
C3V C4 C5 C6 C25 C26 C27: library part C0031-A.9, "CAP CHIP 0402 2.2uF 6.3V X5R 10%", Case Code (Imperial)=0402, Case Code (Metric)=1005, Dielectric=X5R, Manufacturer=Murata, Tolerance=10%, Voltage=6.3V
C4V C5V: library part C0037-A.9, "CAP CHIP 0402 4.7uF 6V3 X5R 20%", Case Code (Imperial)=0402, Case Code (Metric)=1005, Dielectric=X5R, Manufacturer=Murata, Tolerance=20%, Voltage=6.3V
C7 C8 C9 C10 C13 C15 C16 C17 C18 C19 C20 C21 C22 C23 C24 C28 C29 C51 C52 C53 C73 C75 C76 C77 C78: library part C0015-A.9, "CAP CHIP 0402 100nF 50V X5R 10%", Case Code (Imperial)=0402, Case Code (Metric)=1005, Dielectric=X5R, Manufacturer=Murata, Tolerance=10%, Voltage=50V
DL1: library part L0007-A.3, "LED SMD 0603 ORANGE604 8mcd DIFF.", Manufacturer=Broadcom
DL2: library part L0014-A.4, "LED RGB DIFFUSED PICOLED SMD", Case Code (Imperial)=0404, Case Code (Metric)=1010, Color=Blue,Green,Red, Forward Current=20mA, Forward Voltage=3V, Lens Color=White, Manufacturer="ROHM Semiconductor", Max Operating Temperature=85°C, Min Operating Temperature=-40°C, Package Quantity=1, Test Current=5mA
J1: library part J0169-A.5
J1V: library part J0042-A.4, "CONN Micro UFL NO PASTE", Manufacturer=Hirose
J2 J3 J6 J7 J8: library part J0171-A.2
J4: library part J0239-A.1
J5: library part J0240-A.2
J10 J11: library part J0010-A.6, "CONN RCPT USB3.1 TYPEC 24POS SMD", Manufacturer=Hirose
J12: library part J0089-A.6, "CONN HEADER SMD 10POS 2x5 1.27MM JTAG", Color=Black, Current Rating=1.75A, Manufacturer=Samtec, Max Operating Temperature=125°C, Min Operating Temperature=-55°C, Package Quantity=1
J15 J16: library part J0249-A.2, "Board Connector, 20 Contact(s), 2 Row(s), Female, Straight, Surface Mount Terminal, Socket GPinto", Manufacturer=Samtec
J19: library part J0244-A.1, "Conn Jack 4 POLES 3.5mm R/a", Manufacturer="Tensility International Corp"
L1: library part I0004-A.3, "FERRITE SMD 0603 18 OHM 1A", Case Code (Imperial)=0603, Case Code (Metric)=1608, Current=1A, DC Resistance (DCR)=4mR, Manufacturer="Taiyo Yuden", Max DC Current=7.5A, Max Operating Temperature=125°C, Min Operating Temperature=-40°C, Package Quantity=1, Test Frequency=100MHz, Tolerance=30%
L1V: library part I0051-A.3, "IND FIXED SMD 0603 2.2uH, 20%,", DC Resistance (DCR)=250mR, Manufacturer=Murata, Max Operating Temperature=85°C, Min Operating Temperature=-40°C, Test Frequency=1MHz, Tolerance=20%
PB2: library part B0013-A.8, "PUSHBUTTON SMD VERTICAL ANCHORS 4x3.4mm", Manufacturer=E-Switch, Max Operating Temperature=85°C, Min Operating Temperature=-35°C
R1 R2 R5 R13: library part R0149-A.2, "RES CHIP 0201 330R 1% 1/20W", Case Code (Imperial)=0201, Case Code (Metric)=0603, Manufacturer=Yageo, Manufacturer 2="Samsung Electro-Mechanics", Manufacturer Part Number 2=RC0603F331CS, Power=50mW, Tolerance=1%
R1V R3 R7 R8: library part R0000-A.8, "RES CHIP 0402 0R 1/16W", Case Code (Imperial)=0402, Case Code (Metric)=1005, Manufacturer=Vishay, Manufacturer 2=Panasonic, Manufacturer Part Number 2=ERJ-S020R00X, Power=63mW, Tolerance=J
R4 R6: library part R0001-A.8, "RES CHIP 0402 100K 1% 1/16W", Case Code (Imperial)=0402, Case Code (Metric)=1005, Manufacturer=Vishay, Manufacturer 2=Panasonic, Manufacturer Part Number 2=ERJ-2RKF1003X, Power=63mW, Tolerance=1%
R9 R10 R11 R12: library part R0131-A.3, "RES CHIP 0805 0R 1/8W", Case Code (Imperial)=0805, Case Code (Metric)=2012, Manufacturer=Vishay, Power=125mW, Tolerance=J
S1: library part S0023-A.1, "SWITCH SLIDE SMT R/A SP3T 0.3A 4VDC", Manufacturer=C&K
U1: library part U0020-A.5, "IC MCU Cortex M7 + Cortex M4", Manufacturer=STMicroelectronics
U1V: library part U0008-A.14, "MODULE WiFi 11b/g/n+BLUETOOTH 4.2 SHIELDED ULTRA SMALL LBEE5KL1DX", Case/Package=SMD/SMT, Current - Receiving=60mA, Current - Transmitting=370mA, Frequency=2.4GHz, Manufacturer=Murata, Max Operating Temperature=70°C, Min Operating Temperature=-30°C
U2: library part U0122-A.2, "IC SDRAM 64 Mb PC133 SDR", Case/Package=TFBGA, Frequency=166MHz, Manufacturer="Alliance Memory", Max Operating Temperature=85°C, Min Operating Temperature=-40°C
U2: library part U0034-A.3, "IC AUTHENTICATION CHIP UDFN8", Manufacturer=Microchip
U4: library part U0120-A.2, "IC FLASH S-NOR 128M", Manufacturer=Macronix
Y1: library part X0002-A.4, "MEMS OSC XO 32.7680KHZ LVCMOS", Current Rating=1.35uA, Frequency=32.768kHz, Frequency Stability=100ppm, Load Capacitance=10pF, Manufacturer=SiTIME, Max Operating Temperature=85°C, Max Supply Current=1.4uA, Max Supply Voltage=3.63V, Min Operating Temperature=-40°C, Min Supply Voltage=1.5V

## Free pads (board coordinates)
  round 3.2 hole 3.2 unplated: MH1(96.52,2.54) MH2(15.24,50.8) MH3(90.17,50.8) MH4(13.996,2.553) MH5(66.04,35.56) MH6(66.066,7.633)

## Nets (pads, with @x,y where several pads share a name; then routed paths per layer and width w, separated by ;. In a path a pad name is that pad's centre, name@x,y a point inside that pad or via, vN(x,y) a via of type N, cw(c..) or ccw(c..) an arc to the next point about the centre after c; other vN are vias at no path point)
+1V8: U1V.36 | length 1.6
  TOP w0.127: 85.66,39.961 87.26,39.961
+3V1: C2.2 C78.2 DL1.A DL2.1 U1.N17 U1.P17 U2.8 U4.8 Y1.3
+3V1SW: C3.2 C4.2 C5.2 C6.2 C7.2 C8.2 C9.2 C10.2 C13.2 C15.2 C16.2 C17.2 C18.2 C19.2 C20.2 C21.2 C22.2 C23.2 C24.2 C28.2 C29.2 C51.2 C52.2 C53.2 C73.2 C75.2 C76.2 C77.2 R4.1 R8.1 R11.2 R12.2 U1.A6 U1.C17 U1.E6 U1.E9 U1.E11 U1.F5 U1.F17 U1.G5 U1.G13 U1.H5 U1.H13 U1.J13 U1.K5 U1.K13 U1.L5 U1.L13 U1.M5 U1.M13 U1.N7 U1.N8 U1.N10 U1.N11 U1.N12 U1.U12 U2.A7 U2.A9 U2.B3 U2.C7 U2.D3 U2.E7 U2.J9 | length 1.6
  TOP w0.127: 85.66,39.707 87.26,39.707
+3V3: C3V.2 C4V.1 U1V.30
BLE_CTRL_DEVICE_WAKE: U1V.39
BLE_CTRL_HOST_WAKE: U1V.38
BLE_CTRL_ON: U1V.14
DSI_CK_N: U1.L17
DSI_CK_P: U1.L16
DSI_D0_N: U1.M17
DSI_D0_P: U1.M16
DSI_D1_N: U1.K17
DSI_D1_P: U1.K16
GND: C1.1 C1V.2 C2.1 C2V.2 C3.1 C3V.1 C4.1 C4V.2 C5.1 C5V.2 C6.1 C7.1 C8.1 C9.1 C10.1 C12.1 C13.1 C15.1 C16.1 C17.1 C18.1 C19.1 C20.1 C21.1 C22.1 C23.1 C24.1 C25.1 C26.1 C27.1 C28.1 C29.1 C30.1 C51.1 C52.1 C53.1 C73.1 C75.1 C76.1 C77.1 C78.1 J1V.GND R1.1 R6.2 R10.1 U1.A1 U1.A17 U1.B2 U1.B6 U1.C10 U1.C13 U1.C16 U1.F1 U1.F2 U1.G2 U1.G7 U1.G8 U1.G9 U1.G10 U1.G11 U1.G16 U1.H7 U1.H8 U1.H9 U1.H10 U1.H11 U1.J3 U1.J7 U1.J8 U1.J9 U1.J10 U1.J11 U1.J16 U1.J17 U1.K7 U1.K8 U1.K9 U1.K10 U1.K11 U1.K15 U1.L7 U1.L8 U1.L9 U1.L10 U1.L11 U1.L15 U1.M15 U1.N16 U1.P1 U1.R4 U1.R8 U1.T12 U1.U1 U1.U17 U1V.1 U1V.12 U1V.19 U1V.21 U1V.29 U1V.32 U1V.33 U1V.35 U1V.40 U1V.42 U1V.43 U1V.44 U1V.45 U1V.46 U2.4 U2.A1 U2.A3 U2.B7 U2.C3 U2.D7 U2.E3 U2.J1 U4.4 Y1.1 Y1.4
NetC1_2: C1.2 R3.2 U1.J2
NetC1V_1: C1V.1 R1V.1 U1V.41
NetC2V_1: C2V.1 J1V.SIG R1V.2
NetC5V_1: C5V.1 L1V.2 U1V.31
NetC12_2: C12.2 R7.2 U1.C2
NetC30_2: C30.2 L1.1 R9.2 U1.L1
NetDL1_C: DL1.C R1.2
NetDL2_2: DL2.2 R5.2
NetDL2_3: DL2.3 R13.2
NetDL2_4: DL2.4 R2.2
NetL1_2: L1.2 R11.1
NetL1V_1: L1V.1 U1V.34
NetR3_1: R3.1
NetR4_2: R4.2 U1.E7
NetR6_1: R6.1 U1.E8
NetR7_1: R7.1
NetR8_2: R8.2 U1.G17
NetR9_1: R9.1 U1.M1
NetR10_2: R10.2 U1.N1
NetR12_1: R12.1 U1.B1
NetU1_J1: U1.J1
NetU1_K1: U1.K1
NetU1V_2: U1V.2
NetU1V_3: U1V.3
NetU1V_4: U1V.4
NetU1V_5: U1V.5
NetU1V_8: U1V.8
NetU1V_9: U1V.9
NetU1V_10: U1V.10
NetU1V_11: U1V.11
NetU1V_20: U1V.20
NetU1V_22: U1V.22
NetU1V_23: U1V.23
NetU1V_24: U1V.24
NetU1V_25: U1V.25
NetU1V_26: U1V.26
NetU1V_37: U1V.37
NetY1_2: Y1.2
PA0: U1.N5
PA1: U1.N4
PA2: U1.N3
PA3: U1.U2
PA4: U1.U3
PA5: U1.T3
PA6: U1.R3
PA7: U1.R5
PA8: U1.E15
PA9: U1.D15
PA10: U1.D14
PA11: U1.E17
PA12: U1.E16
PA13: U1.C15
PA14: U1.B14
PA15: U1.A14
PB0: U1.U5
PB1: U1.T5
PB2: U1.R6
PB3: U1.C6
PB4: U1.B7
PB5: U1.A5
PB6: U1.B5
PB7: U1.C5
PB8: U1.D5
PB9: U1.D4
PB10: U1.P11
PB11: U1.P12
PB12: U1.T14
PB13: U1.U14
PB14: U1.U15
PB15: U1.T15
PC0: U1.L2
PC1: U1.M2
PC2: U1.M3
PC3: U1.M4
PC4: U1.T4
PC5: U1.U4
PC6: U1.F14
PC7: U1.F13
PC8: U1.E13
PC9: U1.E14
PC10: U1.A13
PC11: U1.B13
PC12: U1.C12
PC13: U1.E3
PD0: U1.D13 U2.C9
PD1: U1.E12 U2.B8
PD2: U1.D12
PD3: U1.B12
PD4: U1.A12
PD5: U1.A11
PD6: U1.B11
PD7: U1.C11
PD8: U1.U16 U2.B2
PD9: U1.T17 U2.B1
PD10: U1.T16 U2.A2
PD11: U1.R15 U4.5
PD12: U1.R16 U4.2
PD13: U1.R17 U4.7
PD14: U1.P16 U2.A8
PD15: U1.P15 U2.B9
PE0: U1.C4 U2.E8
PE1: U1.B4 U2.F1
PE2: U1.C3
PE3: U1.D3
PE4: U1.D2
PE5: U1.D1
PE6: U1.E5
PE7: U1.U9 U2.C8
PE8: U1.T9 U2.D9
PE9: U1.P9 U2.D8
PE10: U1.N9 U2.E9
PE11: U1.P10 U2.E1
PE12: U1.R10 U2.D2
PE13: U1.T10 U2.D1
PE14: U1.U10 U2.C2
PE15: U1.R11 U2.C1
PF0: U1.G4 U2.H7
PF1: U1.G3 U2.H8
PF2: U1.G1 U2.J8
PF3: U1.H4 U2.J7
PF4: U1.J5 U2.J3
PF5: U1.J4 U2.J2
PF6: U1.K2
PF7: U1.K3 U4.3
PF8: U1.K4
PF9: U1.L4
PF10: U1.L3 U4.6
PF11: U1.T7 U2.F8
PF12: U1.R7 U2.H3
PF13: U1.P7 U2.H2
PF14: U1.P8 U2.H1
PF15: U1.R9 U2.G3
PG0: U1.T8 U2.H9
PG1: U1.U8 U2.G2
PG2: U1.H16 U2.G1
PG3: U1.H15
PG4: U1.H14 U2.G7
PG5: U1.G14 U2.G8
PG6: U1.G15 U4.1
PG7: U1.F16
PG8: U1.F15 U2.F2
PG9: U1.A10
PG10: U1.A9
PG11: U1.B9
PG12: U1.C9
PG13: U1.D9
PG14: U1.D8
PG15: U1.D6 U2.F7
PH2: U1.N2 U2.F3
PH3: U1.P2 U2.G9
PH4: U1.P3
PH5: U1.P4 U2.F9
PH6: U1.T11
PH7: U1.U13
PH8: U1.T13
PH9: U1.R13
PH10: U1.P13
PH11: U1.P14
PH12: U1.R14
PH13: U1.D16
PH14: U1.B17
PH15: U1.B16
PI0: U1.A16
PI1: U1.A15
PI2: U1.B15
PI3: U1.C14
PI4: U1.A4
PI5: U1.A3
PI6: U1.A2
PI7: U1.B3
PI8: U1.E4
PI9: U1.E2
PI10: U1.F3
PI11: U1.F4
PI12: U1.H1
PI13: U1.H2
PI14: U1.H3
PI15: U1.P5
PJ0: U1.N6
PJ1: U1.P6
PJ2: U1.T6
PJ3: U1.U6
PJ4: U1.U7
PJ5: U1.R12
PJ6: U1.N15
PJ7: U1.N14
PJ8: U1.N13
PJ9: U1.M14
PJ10: U1.L14
PJ11: U1.K14
PJ12: U1.D11
PJ13: U1.E10
PJ14: U1.D10
PJ15: U1.B10
PK0: U1.J14
PK1: U1.J15
PK2: U1.H17
PK3: U1.C8
PK4: U1.B8
PK5: R5.1 U1.A8
PK6: R2.1 U1.C7
PK7: R13.1 U1.D7
SCL: U2.6
SDA: U2.5
VCAP_A7: C27.2 U1.A7
VCAP_D17: C26.2 U1.D17
VCAP_U11: C25.2 U1.U11
WIFI_CTRL_HOST_WAKE: U1V.27
WIFI_CTRL_ON: U1V.28
pads on no net: J1.1 J1.2 J1.3 J1.4 J1.5 J1.6 J1.7 J1.8 J1.9 J1.10 J2.1 J2.2 J2.3 J2.4 J2.5 J2.6 J2.7 J2.8 J3.1 J3.2 J3.3 J3.4 J3.5 J3.6 J3.7 J3.8 J4.1 J4.2 J4.3 J4.4 J4.5 J4.6 J4.7 J4.8 J4.9 J4.10 J4.11 J4.12 J4.13 J4.14 J4.15 J4.16 J4.17 J4.18 J4.19 J4.20 J4.21 J4.22 J4.23 J4.24 J4.25 J4.26 J4.27 J4.28 J4.29 J4.30 J4.31 J4.32 J4.33 J4.34 J4.35 J4.36 J5.1 J5.2 J5.3 J5.4 J5.5 J5.6 J6.1 J6.2 J6.3 J6.4 J6.5 J6.6 J6.7 J6.8 J7.1 J7.2 J7.3 J7.4 J7.5 J7.6 J7.7 J7.8 J8.1 J8.2 J8.3 J8.4 J8.5 J8.6 J8.7 J8.8 J10.A1 J10.A2 J10.A3 J10.A4 J10.A5 J10.A6 J10.A7 J10.A8 J10.A9 J10.A10 J10.A11 J10.A12 J10.B1 J10.B2 J10.B3 J10.B4 J10.B5 J10.B6 J10.B7 J10.B8 J10.B9 J10.B10 J10.B11 J10.B12 J10.FIXING J10.SHIELD1 J10.SHIELD2 J10.SHIELD3 J10.SHIELD4 J11.A1 J11.A2 J11.A3 J11.A4 J11.A5 J11.A6 J11.A7 J11.A8 J11.A9 J11.A10 J11.A11 J11.A12 J11.B1 J11.B2 J11.B3 J11.B4 J11.B5 J11.B6 J11.B7 J11.B8 J11.B9 J11.B10 J11.B11 J11.B12 J11.FIXING J11.SHIELD1 J11.SHIELD2 J11.SHIELD3 J11.SHIELD4 J12.1 J12.2 J12.3 J12.4 J12.5 J12.6 J12.7 J12.8 J12.9 J12.10 J15.0 J15.1 J15.2 J15.3 J15.4 J15.5 J15.6 J15.7 J15.8 J15.9 J15.10 J15.11 J15.12 J15.13 J15.14 J15.15 J15.16 J15.17 J15.18 J15.19 J15.20 J16.0 J16.1 J16.2 J16.3 J16.4 J16.5 J16.6 J16.7 J16.8 J16.9 J16.10 J16.11 J16.12 J16.13 J16.14 J16.15 J16.16 J16.17 J16.18 J16.19 J16.20 J19.1 J19.2 J19.3 J19.4 J19.NC1 J19.NC2 PB2.1 PB2.2 PB2.3 PB2.MNT PB2.NC1 PB2.NC2 S1. S1.1 S1.2 S1.3 S1.4 U1.C1 U1.E1 U1.R1 U1.R2 U1.T1 U1.T2 U1V.6 U1V.7 U1V.13 U1V.15 U1V.16 U1V.17 U1V.18 U2.1 U2.2 U2.3 U2.7 U2.9 U2.E2 U4.9
copper on no net: | length 92.8
  TOP w0.127: 85.66,40.215 87.26,40.215 ; 85.66,40.469 87.26,40.469 ; 85.66,40.723 87.26,40.723 ; 85.66,40.977 87.26,40.977 ; 85.66,41.231 87.26,41.231 ; 85.66,41.485 87.26,41.485 ; 85.66,41.739 87.26,41.739 ; 85.66,41.993 87.26,41.993 ; 85.66,42.247 87.26,42.247 ; 85.66,42.501 87.26,42.501 ; 85.66,42.755 87.26,42.755 ; 85.66,43.009 87.26,43.009 ; 85.66,43.263 87.26,43.263 ; 85.66,43.517 87.26,43.517 ; 85.66,43.771 87.26,43.771 ; 85.66,44.025 87.26,44.025 ; 85.66,44.279 87.26,44.279 ; 85.66,44.533 87.26,44.533 ; 85.66,44.787 87.26,44.787 ; 85.66,45.041 87.26,45.041 ; 85.66,45.295 87.26,45.295 ; 85.66,45.549 87.26,45.549 ; 85.66,45.803 87.26,45.803 ; 85.66,46.057 87.26,46.057 ; 85.66,46.311 87.26,46.311 ; 85.66,46.565 87.26,46.565 ; 85.66,46.819 87.26,46.819 ; 85.66,47.073 87.26,47.073
  BOTTOM w0.127: 85.66,39.739 87.26,39.739 ; 85.66,39.993 87.26,39.993 ; 85.66,40.247 87.26,40.247 ; 85.66,40.501 87.26,40.501 ; 85.66,40.755 87.26,40.755 ; 85.66,41.009 87.26,41.009 ; 85.66,41.263 87.26,41.263 ; 85.66,41.517 87.26,41.517 ; 85.66,41.771 87.26,41.771 ; 85.66,42.025 87.26,42.025 ; 85.66,42.279 87.26,42.279 ; 85.66,42.533 87.26,42.533 ; 85.66,42.787 87.26,42.787 ; 85.66,43.041 87.26,43.041 ; 85.66,43.295 87.26,43.295 ; 85.66,43.549 87.26,43.549 ; 85.66,43.803 87.26,43.803 ; 85.66,44.057 87.26,44.057 ; 85.66,44.311 87.26,44.311 ; 85.66,44.565 87.26,44.565 ; 85.66,44.819 87.26,44.819 ; 85.66,45.073 87.26,45.073 ; 85.66,45.327 87.26,45.327 ; 85.66,45.581 87.26,45.581 ; 85.66,45.835 87.26,45.835 ; 85.66,46.089 87.26,46.089 ; 85.66,46.343 87.26,46.343 ; 85.66,46.597 87.26,46.597 ; 85.66,46.851 87.26,46.851 ; 85.66,47.105 87.26,47.105

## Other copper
TOP:
  text "30 tracks / 5mil/5mil" at 77.66,41.739 h0.8

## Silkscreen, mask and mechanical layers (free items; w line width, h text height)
Top Overlay:
  drawing of 27 lines, arcs and shapes, not listed
  text "ON" at 4.758,51.828 h1.3
  text "OFF" at 2.345,51.701 h1.3
  text "RESET" at 8.626,51.701 h1.3
  text "9" at 39.834,48.26 h1.8 r90
  text "8" at 42.374,48.26 h1.8 r90
  text "11" at 34.754,47.677 h1.8 r90
  text "12" at 32.214,47.496 h1.8 r90
  text "10" at 37.294,47.494 h1.8 r90
  text "22" at 90.67,47.494 h1.8
  text "13" at 29.747,47.279 h1.8 r90
  text "7" at 46.485,47.083 h1.8 r90
  text "6" at 49.025,47.083 h1.8 r90
  text "5" at 51.565,47.083 h1.8 r90
  text "4" at 54.105,47.083 h1.8 r90
  text "3" at 56.645,47.083 h1.8 r90
  text "2" at 59.185,47.083 h1.8 r90
  text "1" at 61.725,47.083 h1.8 r90
  text "0" at 64.265,47.083 h1.8 r90
  text "14" at 69.345,47.083 h1.8 r90
  text "15" at 71.885,47.083 h1.8 r90
  text "16" at 74.425,47.083 h1.8 r90
  text "17" at 76.965,47.083 h1.8 r90
  text "18" at 79.505,47.083 h1.8 r90
  text "19" at 82.045,47.083 h1.8 r90
  text "20" at 84.585,47.083 h1.8 r90
  text "21" at 87.125,47.083 h1.8 r90
  text "SCL1" at 19.514,45.098 h1.8 r90
  text "24" at 90.67,44.954 h1.8
  text "SDA1" at 22.054,44.918 h1.8 r90
  text "GND" at 27.192,44.897 h1.8 r90
  text "AREF" at 24.594,44.587 h1.8 r90
  text "26" at 90.67,42.414 h1.8
  text "AUDIO IN/OUT" at 13.181,40.601 h1.8
  text "28" at 90.67,39.874 h1.8
  text "54" at 13.1,37.335 h1.8
  text "55" at 23.26,37.335 h1.8
  text "72" at 76.6,37.334 h1.8
  text "73" at 86.76,37.334 h1.8
  text "30" at 90.67,37.334 h1.8
  text "31" at 98.19,37.334 h1.8
  text "56" at 13.1,34.795 h1.8
  text "57" at 23.26,34.795 h1.8
  text "74" at 76.6,34.794 h1.8
  text "75" at 86.76,34.794 h1.8
  text "32" at 90.67,34.794 h1.8
  text "33" at 98.19,34.794 h1.8
  text "60" at 13.1,32.255 h1.8
  text "61" at 23.37,32.255 h1.8
  text "DSI" at 75.665,32.254 h1.8
  text "DSI" at 86.76,32.254 h1.8
  text "34" at 90.67,32.254 h1.8
  text "35" at 98.19,32.254 h1.8
  text "GND" at 74.893,29.729 h1.8
  text "GND" at 86.193,29.729 h1.8
  text "62" at 13.1,29.715 h1.8
  text "63" at 23.26,29.715 h1.8
  text "36" at 90.67,29.714 h1.8
  text "37" at 98.19,29.714 h1.8
  text "65" at 23.26,27.181 h1.8
  text "64" at 13.1,27.175 h1.8
  text "DSI" at 75.937,27.174 h1.8
  text "DSI" at 86.87,27.174 h1.8
  text "38" at 90.67,27.174 h1.8
  text "39" at 98.19,27.174 h1.8
  text "USB1" at 10.783,25.771 h1.8 r90
  text "66" at 13.002,24.635 h1.8
  text "67" at 23.26,24.635 h1.8
  text "DSI" at 75.937,24.634 h1.8
  text "DSI" at 86.76,24.634 h1.8
  text "40" at 90.67,24.634 h1.8
  text "41" at 98.19,24.634 h1.8
  text "GND" at 74.893,22.109 h1.8
  text "GND" at 86.193,22.109 h1.8
  text "68" at 13.1,22.095 h1.8
  text "69" at 23.26,22.095 h1.8
  text "42" at 90.67,22.094 h1.8
  text "43" at 98.19,22.094 h1.8
  text "70" at 13.1,19.555 h1.8
  text "71" at 23.26,19.555 h1.8
  text "76" at 76.6,19.554 h1.8
  text "77" at 86.76,19.554 h1.8
  text "44" at 90.67,19.554 h1.8
  text "45" at 98.19,19.554 h1.8
  text "GND" at 23.293,17.029 h1.8
  text "3V3" at 12.165,17.014 h1.8
  text "78" at 76.6,17.014 h1.8
  text "79" at 86.76,17.014 h1.8
  text "46" at 90.67,17.014 h1.8
  text "47" at 98.19,17.014 h1.8
  text "SCL1" at 11.103,14.474 h1.8
  text "SDA1" at 23.26,14.474 h1.8
  text "80" at 76.6,14.474 h1.8
  text "81" at 86.76,14.474 h1.8
  text "48" at 90.67,14.474 h1.8
  text "49" at 98.19,14.474 h1.8
  text "USB0" at 10.783,12.69 h1.8 r90
  text "50" at 90.67,11.934 h1.8
  text "51" at 98.19,11.934 h1.8
  text "GIGA" at 51.068,11.041 h4
  text "52" at 90.67,9.394 h1.8
  text "53" at 98.19,9.394 h1.8
  text "GND" at 93.98,6.869 h1.6
  text "NTC VBAT" at 29.243,4.349 h1.8 r90
  text "IOREF" at 31.245,4.349 h1.8 r90
  text "RESET" at 33.785,4.349 h1.8 r90
  text "3V3" at 36.325,4.349 h1.8 r90
  text "5V" at 38.865,4.349 h1.8 r90
  text "VIN" at 46.485,4.349 h1.8 r90
  text "A0" at 51.565,4.349 h1.8 r90
  text "A1" at 54.105,4.349 h1.8 r90
  text "A2" at 56.645,4.349 h1.8 r90
  text "A3" at 59.185,4.349 h1.8 r90
  text "A4" at 61.725,4.349 h1.8 r90
  text "A5" at 64.265,4.349 h1.8 r90
  text "A6" at 66.805,4.349 h1.4 r90
  text "A7" at 69.345,4.349 h1.8 r90
  text "A8" at 74.425,4.349 h1.8 r90
  text "A9" at 76.965,4.349 h1.8 r90
  text "A10" at 79.505,4.349 h1.8 r90
  text "A11" at 82.045,4.349 h1.8 r90
  text "DAC2" at 84.585,4.349 h1.8 r90
  text "DAC1" at 87.125,4.349 h1.8 r90
  text "CANRX" at 89.665,4.349 h1.5 r90
  text "CANTX" at 92.205,4.349 h1.5 r90
  text "BOOT0" at 5.83,3.546 h1.8 r90
  text "GND" at 41.416,2.553 h1.8 r90
  text "GND" at 43.956,2.553 h1.8 r90
Route Tool Path:
  lines w2: -1,29.75 -1,22.47 -1,1 ccw(c1,1) 1,-1 42.3,-1 48.8,-1 ; -1,33.75 -1,40.25 -1,52.34 cw(c1,52.34) 1,54.34 41.52,54.34 48.8,54.34 ; 52.8,-1 60.08,-1 98.06,-1 ccw(c98.06,1) 100.06,1 100.06,2.126 102.307,4.373 ; 52.8,54.34 59.3,54.34 97.536,54.34 ; 102.6,19.096 102.6,12.596 102.6,5.08 ; 102.6,23.096 102.6,30.376 102.6,37.846 ; 97.536,54.34 cw(c97.536,53.34) 98.243,54.047 ; 97.536,54.34 cw(c97.536,53.34) 98.243,54.047 ; 98.243,54.047 99.767,52.523 ; 99.767,52.523 cw(c99.06,51.816) 100.06,51.816 ; 99.767,52.523 cw(c99.06,51.816) 100.06,51.816 ; 100.06,51.816 100.06,40.8 102.307,38.553 ; 102.307,4.373 ccw(c101.6,5.08) 102.6,5.08 ; 102.307,4.373 ccw(c101.6,5.08) 102.6,5.08 ; 102.307,38.553 cw(c101.6,37.846) 102.6,37.846 ; 102.307,38.553 cw(c101.6,37.846) 102.6,37.846
Board:
  the board outline again, w0.254
Mechanical 9:
  lines w0.1: 6.194,2.927 7.464,2.927 ; 7.464,1.657 7.464,2.927 ; 7.464,4.197 7.464,2.927 ; 8.734,2.927 7.464,2.927 ; 17.552,50.813 18.822,50.813 ; 18.822,49.543 18.822,50.813 ; 18.822,52.083 18.822,50.813 ; 20.092,50.813 18.822,50.813 ; 26.696,2.553 27.966,2.553 ; 27.966,1.283 27.966,2.553 ; 27.966,3.823 27.966,2.553 ; 29.236,2.553 27.966,2.553 ; 44.476,50.813 45.746,50.813 ; 45.746,49.543 45.746,50.813 ; 45.746,52.083 45.746,50.813 ; 47.016,50.813 45.746,50.813 ; 49.556,2.553 50.826,2.553 ; 50.826,1.283 50.826,2.553 ; 50.826,3.823 50.826,2.553 ; 52.096,2.553 50.826,2.553 ; 62.357,30.48 63.627,30.48 ; 63.627,29.21 63.627,30.48 ; 63.627,31.75 63.627,30.48 ; 64.897,30.48 63.627,30.48 ; 67.336,50.813 68.606,50.813 ; 68.606,49.543 68.606,50.813 ; 68.606,52.083 68.606,50.813 ; 69.876,50.813 68.606,50.813 ; 72.416,2.553 73.686,2.553 ; 73.686,1.283 73.686,2.553 ; 73.686,3.823 73.686,2.553 ; 74.956,2.553 73.686,2.553 ; 92.71,50.799 93.98,50.799 ; 93.98,49.529 93.98,50.799 ; 93.98,52.069 93.98,50.799 ; 95.25,50.799 93.98,50.799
